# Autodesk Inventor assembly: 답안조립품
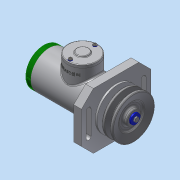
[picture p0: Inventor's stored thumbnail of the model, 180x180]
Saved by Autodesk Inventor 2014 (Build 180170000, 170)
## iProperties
Created: 2017-10
Part Number: 답안조립품
Document SubType Name: Assembly
Designer: kb542-18
Author: kb542-18
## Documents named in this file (20)
- C:\Users\kb542-18\Desktop\471007V1021\답안조립품.iam
- C:\Users\kb542-18\Desktop\471007V1021\본체.ipt
- C:\Users\kb542-18\Desktop\471007V1021\V-벨트풀리.ipt
- C:\Users\kb542-18\Desktop\471007V1021\너트 M10.ipt
- C:\Users\kb542-18\Desktop\471007V1021\멈춤링 15 x 1.ipt
- C:\Users\kb542-18\Desktop\471007V1021\멈춤링 35x1.6.ipt
- C:\Users\kb542-18\Desktop\471007V1021\베어링 15 x 35 x 11.ipt
- C:\Users\kb542-18\Desktop\471007V1021\볼트 M4 x 10.ipt
- C:\Users\kb542-18\Desktop\471007V1021\부시1.ipt
- C:\Users\kb542-18\Desktop\471007V1021\부시2.ipt
- C:\Users\kb542-18\Desktop\471007V1021\사이드 커버.ipt
- 사이드 커버.ipt
- C:\Users\kb542-18\Desktop\471007V1021\십자볼트 M3 x 10.ipt
- C:\Users\kb542-18\Desktop\471007V1021\오일 실 15 25 7.ipt
- C:\Users\kb542-18\Desktop\471007V1021\와셔 3x6.ipt
- C:\Users\kb542-18\Desktop\471007V1021\와셔 4x16.ipt
- C:\Users\kb542-18\Desktop\471007V1021\와셔 10x21.ipt
- C:\Users\kb542-18\Desktop\471007V1021\축.ipt
- C:\Users\kb542-18\Desktop\471007V1021\키 4 x 4 x 18.ipt
- C:\Users\kb542-18\Desktop\471007V1021\탑 커버.ipt
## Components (2 placed, 2 different names)
1. V-벨트풀리:1 — 각도:2
2. ISO 4017 M4 x 10:1 — 각도:6
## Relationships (2: Angle 2)
- 각도:2 [Angle]: V-벨트풀리:1
- 각도:6 [Angle]: ISO 4017 M4 x 10:1
